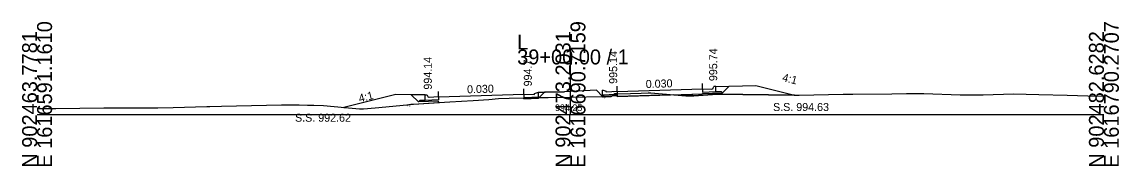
# Model space of a CAD drawing. Extents: x 1009 to 7438, y -1586 to 7964.
# Drawn here: x 3032.1 to 3237.7, y 6914 to 6941.1 of the extents above; entities that cross this region are included whole.
import ezdxf

# ---------------------------------------------------------------- set-up
doc = ezdxf.new("R2010")
doc.units = 0
for name, color, linetype in [('Exist Cross Section Cell', 7, 'Continuous'), ('Exist XS Center Line Elevation Label', 7, 'Continuous'), ('Exist XS Ground Line', 7, 'Continuous'), ('Prop XS Dump Level', 7, 'Continuous'), ('Prop XS Earthwork Shape', 7, 'Continuous'), ('Prop XS EOT Tick Mark', 7, 'Continuous'), ('Prop XS Finish Grade', 7, 'Continuous'), ('Prop XS Finish Grade CurbGutter', 7, 'Continuous'), ('Prop XS Finish Grade Earthwork', 7, 'Continuous'), ('Prop XS Finish Grade Pavement', 7, 'Continuous'), ('Prop XS Hydro Elevations', 7, 'Continuous'), ('Prop XS Pvmt Edge Slope', 7, 'Continuous'), ('Prop XS SE Text', 7, 'Continuous'), ('Prop XS Side Slope Text', 7, 'Continuous'), ('Prop XS SS Elevation Text', 7, 'Continuous'), ('Prop XS Subgrade CurbGutter', 7, 'Continuous'), ('Prop XS Subgrade Earthwork', 7, 'Continuous')]:
    doc.layers.add(name, color=color, linetype=linetype)

msp = doc.modelspace()

# ---------------------------------------------------------------- linework, layer by layer
at = {"layer": 'Exist Cross Section Cell'}
for p, q in [((3134.89, 6923.73), (3134.89, 6935.9)), ((3034.89, 6923.73), (3134.89, 6923.73)), ((3134.89, 6923.73), (3234.89, 6923.73))]:
    msp.add_line(p, q, dxfattribs=at)
at = {"layer": 'Exist XS Ground Line'}
for p, q in [((3142.46, 6927.08), (3143.22, 6927.58)), ((3143.22, 6927.58), (3146.12, 6927.65)), ((3146.12, 6927.65), (3148.17, 6927.7)), ((3148.17, 6927.7), (3149.45, 6927.76)), ((3149.45, 6927.76), (3149.95, 6927.78)), ((3149.95, 6927.78), (3156.53, 6927.21)), ((3158.04, 6927.19), (3162.36, 6927.54)), ((3162.36, 6927.54), (3176.81, 6927.31)), ((3177.78, 6927.33), (3185.99, 6927.52)), ((3185.99, 6927.52), (3187.83, 6927.54)), ((3187.83, 6927.54), (3195.16, 6927.61)), ((3195.16, 6927.61), (3197.87, 6927.66)), ((3197.87, 6927.66), (3201.15, 6927.66)), ((3201.15, 6927.66), (3207.92, 6927.4)), ((3207.92, 6927.4), (3212.25, 6927.37)), ((3212.25, 6927.37), (3217.96, 6927.56)), ((3217.96, 6927.56), (3222.69, 6927.45)), ((3222.69, 6927.45), (3228.01, 6927.36)), ((3228.01, 6927.36), (3231.87, 6927.23)), ((3069.45, 6925.26), (3080.73, 6925.51)), ((3080.73, 6925.51), (3084.01, 6925.49)), ((3084.01, 6925.49), (3085.61, 6925.48)), ((3085.61, 6925.48), (3086.76, 6925.47)), ((3086.76, 6925.47), (3088.58, 6925.42)), ((3088.58, 6925.42), (3092.61, 6925.03)), ((3098.29, 6924.96), (3104.22, 6925.53)), ((3104.22, 6925.53), (3104.98, 6925.62)), ((3104.98, 6925.62), (3105.45, 6925.67)), ((3105.45, 6925.67), (3112.26, 6926.07)), ((3112.26, 6926.07), (3116.62, 6926.32)), ((3116.62, 6926.32), (3119.56, 6926.55)), ((3119.56, 6926.55), (3121.42, 6926.69)), ((3121.42, 6926.69), (3123.41, 6926.76)), ((3123.41, 6926.76), (3126.43, 6926.86)), ((3126.43, 6926.86), (3134.95, 6926.98)), ((3134.95, 6926.98), (3140.76, 6927.08)), ((3140.76, 6927.08), (3141.77, 6927.09)), ((3141.77, 6927.09), (3142.46, 6927.08)), ((3156.53, 6927.21), (3158.04, 6927.19)), ((3176.81, 6927.31), (3177.78, 6927.33)), ((3231.87, 6927.23), (3234.89, 6927.15)), ((3034.89, 6924.81), (3038.08, 6924.83)), ((3038.08, 6924.83), (3038.39, 6924.84)), ((3038.39, 6924.84), (3047.43, 6924.95)), ((3047.43, 6924.95), (3057.1, 6924.97)), ((3057.1, 6924.97), (3057.52, 6924.97)), ((3057.52, 6924.97), (3060.42, 6925.04)), ((3060.42, 6925.04), (3066.69, 6925.2)), ((3066.69, 6925.2), (3067.29, 6925.21)), ((3067.29, 6925.21), (3069.45, 6925.26)), ((3092.61, 6925.03), (3095.33, 6924.77)), ((3095.33, 6924.77), (3096.08, 6924.76)), ((3096.08, 6924.76), (3098.29, 6924.96))]:
    msp.add_line(p, q, dxfattribs=at)
at = {"layer": 'Prop XS Dump Level'}
for p, q in [((3110.14, 6927.01), (3126.14, 6927.49)), ((3110.14, 6927.01), (3126.14, 6927.49)), ((3143.64, 6928.01), (3159.64, 6928.49)), ((3143.64, 6928.01), (3159.64, 6928.49))]:
    msp.add_line(p, q, dxfattribs=at)
at = {"layer": 'Prop XS Earthwork Shape'}
for points in [[(3105.45, 6925.67), (3110.14, 6925.95), (3110.14, 6926.09), (3110.14, 6926.18), (3106.39, 6926.06), (3105.04, 6927.42), (3102.14, 6927.48), (3092.42, 6925.05), (3092.61, 6925.03), (3095.33, 6924.77), (3096.08, 6924.76), (3098.29, 6924.96), (3104.22, 6925.53), (3104.98, 6925.62)], [(3142.46, 6927.08), (3142.56, 6927.15), (3140.88, 6927.1), (3139.74, 6928.24), (3133.76, 6927.97), (3130.12, 6927.89), (3130.04, 6927.89), (3129.04, 6926.9), (3134.95, 6926.98), (3140.76, 6927.08), (3141.77, 6927.09)], [(3143.64, 6927.18), (3142.56, 6927.15), (3142.96, 6927.41), (3143.64, 6927.43)], [(3143.64, 6927.43), (3143.64, 6927.59), (3143.22, 6927.58), (3142.96, 6927.41)], [(3143.64, 6927.43), (3143.64, 6927.59), (3146.12, 6927.65), (3148.17, 6927.7), (3149.45, 6927.76), (3149.95, 6927.78), (3154.2, 6927.41), (3143.64, 6927.1), (3143.64, 6927.18)], [(3154.2, 6927.41), (3159.64, 6927.58), (3159.64, 6927.66), (3163.39, 6927.77), (3164.64, 6929.02), (3169.64, 6929.13), (3176.91, 6927.31), (3176.81, 6927.31), (3162.36, 6927.54), (3158.04, 6927.19), (3156.53, 6927.21)], [(3126.14, 6926.66), (3128.89, 6926.74), (3128.73, 6926.89), (3126.43, 6926.86), (3126.14, 6926.85)], [(3128.73, 6926.89), (3129.04, 6926.9), (3128.89, 6926.74)]]:
    msp.add_lwpolyline(points, close=True, dxfattribs=at)
at = {"layer": 'Prop XS EOT Tick Mark'}
for p, q in [((3159.64, 6928.49), (3159.64, 6929.49)), ((3110.14, 6927.01), (3110.14, 6928.01)), ((3126.14, 6927.49), (3126.14, 6928.49)), ((3143.64, 6928.01), (3143.64, 6929.01))]:
    msp.add_line(p, q, dxfattribs=at)
at = {"layer": 'Prop XS Finish Grade'}
for p, q in [((3107.64, 6927.37), (3105.04, 6927.42)), ((3128.89, 6927.87), (3130.12, 6927.89)), ((3162.14, 6928.97), (3164.64, 6929.02))]:
    msp.add_line(p, q, dxfattribs=at)
at = {"layer": 'Prop XS Finish Grade CurbGutter'}
for p, q in [((3107.64, 6927.37), (3107.89, 6927.37)), ((3107.89, 6927.37), (3108.02, 6927.34)), ((3126.14, 6927.49), (3128.14, 6927.45)), ((3128.14, 6927.62), (3128.89, 6927.87)), ((3128.14, 6927.45), (3128.14, 6927.62)), ((3141.65, 6928.04), (3140.9, 6928.29)), ((3141.65, 6927.87), (3141.65, 6928.04)), ((3143.64, 6928.01), (3141.65, 6927.87)), ((3143.64, 6928.01), (3142.89, 6927.96)), ((3159.64, 6928.49), (3161.39, 6928.47)), ((3161.39, 6928.47), (3161.52, 6928.5)), ((3161.52, 6928.5), (3161.61, 6928.59)), ((3161.61, 6928.59), (3161.68, 6928.84)), ((3161.68, 6928.84), (3161.77, 6928.93)), ((3161.89, 6928.97), (3161.77, 6928.93)), ((3162.14, 6928.97), (3161.89, 6928.97)), ((3108.11, 6927.25), (3108.02, 6927.34)), ((3108.18, 6927), (3108.11, 6927.25)), ((3108.27, 6926.91), (3108.18, 6927)), ((3108.39, 6926.88), (3108.27, 6926.91)), ((3110.14, 6927.01), (3108.39, 6926.88))]:
    msp.add_line(p, q, dxfattribs=at)
at = {"layer": 'Prop XS Finish Grade Earthwork'}
for p, q in [((3102.14, 6927.48), (3092.42, 6925.05)), ((3105.04, 6927.42), (3102.14, 6927.48)), ((3130.12, 6927.89), (3133.76, 6927.97)), ((3139.74, 6928.24), (3133.76, 6927.97)), ((3164.64, 6929.02), (3169.64, 6929.13)), ((3169.64, 6929.13), (3176.91, 6927.31))]:
    msp.add_line(p, q, dxfattribs=at)
at = {"layer": 'Prop XS Finish Grade Pavement'}
for p, q in [((3110.14, 6927.01), (3126.14, 6927.49)), ((3143.64, 6928.01), (3159.64, 6928.49))]:
    msp.add_line(p, q, dxfattribs=at)
at = {"layer": 'Prop XS Pvmt Edge Slope'}
for p, q in [((3141.14, 6927.36), (3140.88, 6927.1)), ((3142.14, 6927.39), (3140.9, 6927.35)), ((3162.14, 6927.99), (3163.14, 6928.02)), ((3163.14, 6928.02), (3163.39, 6927.77)), ((3106.64, 6926.32), (3106.39, 6926.06)), ((3107.64, 6926.35), (3106.64, 6926.32)), ((3127.64, 6926.94), (3128.67, 6926.96)), ((3127.64, 6926.94), (3128.89, 6926.96)), ((3128.67, 6926.96), (3128.89, 6926.74))]:
    msp.add_line(p, q, dxfattribs=at)
at = {"layer": 'Prop XS Subgrade CurbGutter'}
for p, q in [((3107.64, 6926.35), (3107.64, 6927.37)), ((3126.14, 6927.49), (3126.14, 6926.91)), ((3128.89, 6926.96), (3128.89, 6927.87)), ((3140.9, 6927.35), (3140.9, 6928.29)), ((3143.64, 6927.43), (3142.14, 6927.39)), ((3143.64, 6928.01), (3143.64, 6927.43)), ((3159.64, 6928.49), (3159.64, 6927.91)), ((3159.64, 6927.91), (3162.14, 6927.99)), ((3162.14, 6927.99), (3162.14, 6928.97)), ((3110.14, 6926.43), (3107.64, 6926.35)), ((3110.14, 6927.01), (3110.14, 6926.43)), ((3126.14, 6926.91), (3127.64, 6926.94))]:
    msp.add_line(p, q, dxfattribs=at)
at = {"layer": 'Prop XS Subgrade Earthwork'}
for p, q in [((3106.39, 6926.06), (3105.04, 6927.42)), ((3128.89, 6926.74), (3130.04, 6927.89)), ((3140.88, 6927.1), (3139.74, 6928.24)), ((3143.64, 6927.1), (3143.64, 6927.59)), ((3143.64, 6927.1), (3143.64, 6927.59)), ((3143.64, 6927.1), (3159.64, 6927.58)), ((3159.64, 6927.66), (3163.39, 6927.77)), ((3159.64, 6927.58), (3159.64, 6927.66)), ((3163.39, 6927.77), (3164.64, 6929.02)), ((3110.14, 6926.18), (3106.39, 6926.06)), ((3110.14, 6926.09), (3110.14, 6926.18)), ((3110.14, 6926.09), (3110.14, 6925.95)), ((3126.14, 6926.66), (3126.14, 6926.85)), ((3126.14, 6926.66), (3128.89, 6926.74)), ((3143.64, 6927.18), (3140.88, 6927.1)), ((3143.64, 6927.1), (3143.64, 6927.18))]:
    msp.add_line(p, q, dxfattribs=at)

# ---------------------------------------------------------------- texts
at = {"layer": 'Exist Cross Section Cell'}
for s, p in [('E 1616591.1610', (3037.69, 6913.73)), ('E 1616690.7159', (3137.69, 6913.73)), ('E 1616790.2707', (3237.69, 6913.73)), ('N 902463.7781', (3034.89, 6913.73)), ('N 902473.2031', (3134.89, 6913.73)), ('N 902482.6282', (3234.89, 6913.73))]:
    msp.add_text(s, height=2.8, rotation=90, dxfattribs=at).set_placement(p)
for s, p in [('L', (3124.89, 6935.9)), ('39+00.00 / 1', (3124.89, 6933.1))]:
    msp.add_text(s, height=2.8, dxfattribs=at).set_placement(p)
at = {"layer": 'Exist XS Center Line Elevation Label'}
msp.add_text('994.25', height=1.25, dxfattribs=at).set_placement((3131.99, 6924.35))
at = {"layer": 'Prop XS Dump Level'}
for p in [(3104.22, 6925.23), (3140.76, 6926.78), (3140.76, 6926.78), (3140.76, 6926.78)]:
    msp.add_text('Eop', height=0.3, dxfattribs=at).set_placement(p)
at = {"layer": 'Prop XS Hydro Elevations'}
for s, p in [('995.74', (3162.39, 6929.97)), ('994.14', (3108.89, 6928.37)), ('994.71', (3127.64, 6928.98)), ('995.14', (3143.64, 6929.46))]:
    msp.add_text(s, height=1.5, rotation=90, dxfattribs=at).set_placement(p)
at = {"layer": 'Prop XS SE Text'}
for p in [(3149.02, 6928.67), (3115.52, 6927.67)]:
    msp.add_text('0.030', height=1.5, rotation=1.7184, dxfattribs=at).set_placement(p)
at = {"layer": 'Prop XS Side Slope Text'}
for rotation, p in [(345.9638, (3174.49, 6930.01)), (14.0362, (3095.37, 6925.96))]:
    msp.add_text('4:1', height=1.5, rotation=rotation, dxfattribs=at).set_placement(p)
at = {"layer": 'Prop XS SS Elevation Text'}
for s, p in [('S.S. 994.63', (3172.87, 6924.36)), ('S.S. 992.62', (3083.25, 6922.35))]:
    msp.add_text(s, height=1.5, dxfattribs=at).set_placement(p)

doc.saveas('drawing.dxf')
